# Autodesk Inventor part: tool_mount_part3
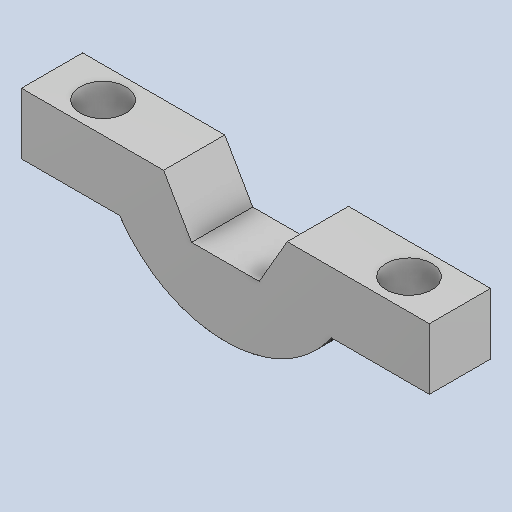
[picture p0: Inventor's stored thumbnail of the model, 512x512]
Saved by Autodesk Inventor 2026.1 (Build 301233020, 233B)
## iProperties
Created: 2026-10
Part Number: tool_mount_part3
Material: Steel
Document SubType Name: Modeling
Designer: hp
Density: 7.85 g/cm^3
Appearance: Default
Author: hp
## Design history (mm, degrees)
feature "Body1"
sketch "Sketch1"
  geometry: 1 further point
hole "Hole1" sketch "Sketch1" at (5, -3) diameter "d0" = 4.5; stored, may be unused: countersink angle "d4" = 90 deg, drill point angle "d6" = 0 deg; dims "d1" = 6, "d2" = 4, "d3" = 2, "d5" = 8
sketch "Sketch2"
  geometry: 1 further point
hole "Hole2" sketch "Sketch2" at (4.642, -3) diameter "d7" = 4.5; stored, may be unused: countersink angle "d11" = 90 deg, drill point angle "d13" = 0 deg; dims "d8" = 6, "d9" = 4, "d10" = 2, "d12" = 8
body "Solid1"
